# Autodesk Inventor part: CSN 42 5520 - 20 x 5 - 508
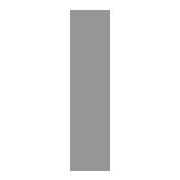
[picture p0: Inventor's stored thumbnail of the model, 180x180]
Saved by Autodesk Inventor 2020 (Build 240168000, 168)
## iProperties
Created: 2019-01
Part Number: CSN 42 5520 - 20 x 5 - 508
Material: Ocel, měkká
Description: Tyč
Document SubType Name: Modeling
Standard: CSN 42 5520
Designer: doma
Standards Organization: CSN
Language: cs-CZ
Size Designation: 20 x 5 - 508
Categories: <MemberInstance><Categories><Category DisplayName="Konstrukční profily" InternalName="089c4875-fa83-4c05-b084-43b9cc11f5ed" Mnemonic="GRDR"><CategoryParameter D
Stock Number: 20 x 5
Density: 7.85 g/cm^3
Appearance: Pololeštěná
IsCustomPart: 1
Author: doma
G_L: 508,000 mm
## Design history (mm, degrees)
node "Počáteční rovina"
node "Koncová rovina"
sketch "Náčrt"
  geometry: L1 (2.5, -10)-(-2.5, -10); L2 (-2.5, -10)-(-2.5, 10); L3 (-2.5, 10)-(2.5, 10); L4 (2.5, 10)-(2.5, -10); L5 (-6, 0)-(8, 0); L6 (0, -30)-(0, 40); L7 (0, 54)-(0, -44) reference; L8 (-9.2, 0)-(13.2, 0) reference
  constraints: 12 end point, 2 collinear, 2 parallel, 1 horizontal, 1 perpendicular
  dimensions: "d0" = 20 distance between parallel lines of L3 L1 (= G_W); "d1" = 5 distance between parallel lines of L4 L2 (= G_H); "d4" = 2.5 distance between parallel lines of L6 L4 (= 0.5 x d1); "d5" = 10 distance between parallel lines of L5 L3 (= 0.5 x d0)
extrude "Těleso" new body sketch "Náčrt" stored distance "d2" = 508 (= G_L); taper "d3" = 0 deg
node "Driven Length"
  sketch "Sketch3"
    geometry: L1 (0, 0)-(10, 0) reference
    constraints: 2 end point, 1 horizontal
  workplane "Work Plane3"
  sketch "Sketch4"
    geometry: L1 (-2, 0)-(12, 0) reference; L2 (-2, 508)-(12, 508) reference
    dimensions: "d9" = 508 distance between parallel lines of L1 L2 (derived)
body "Solid1"
other parameters: "G_W" = 20 [user parameter; used in 1 equation term], "G_H" = 5 [user parameter; used in 1 equation term], "G_L" = 508 (= d9) [user parameter; used in 1 equation term], "G_OFFSET_START" = 0 [user parameter; used in 1 equation term], "G_OFFSET_END" = 0 [user parameter; used in 1 equation term], "d6" = 0 (computed from G_OFFSET_START), "d7" = 508 (= G_OFFSET_END + B_L), "B_L" = 508 [user parameter; used in 1 equation term], "d8" = 90 deg
